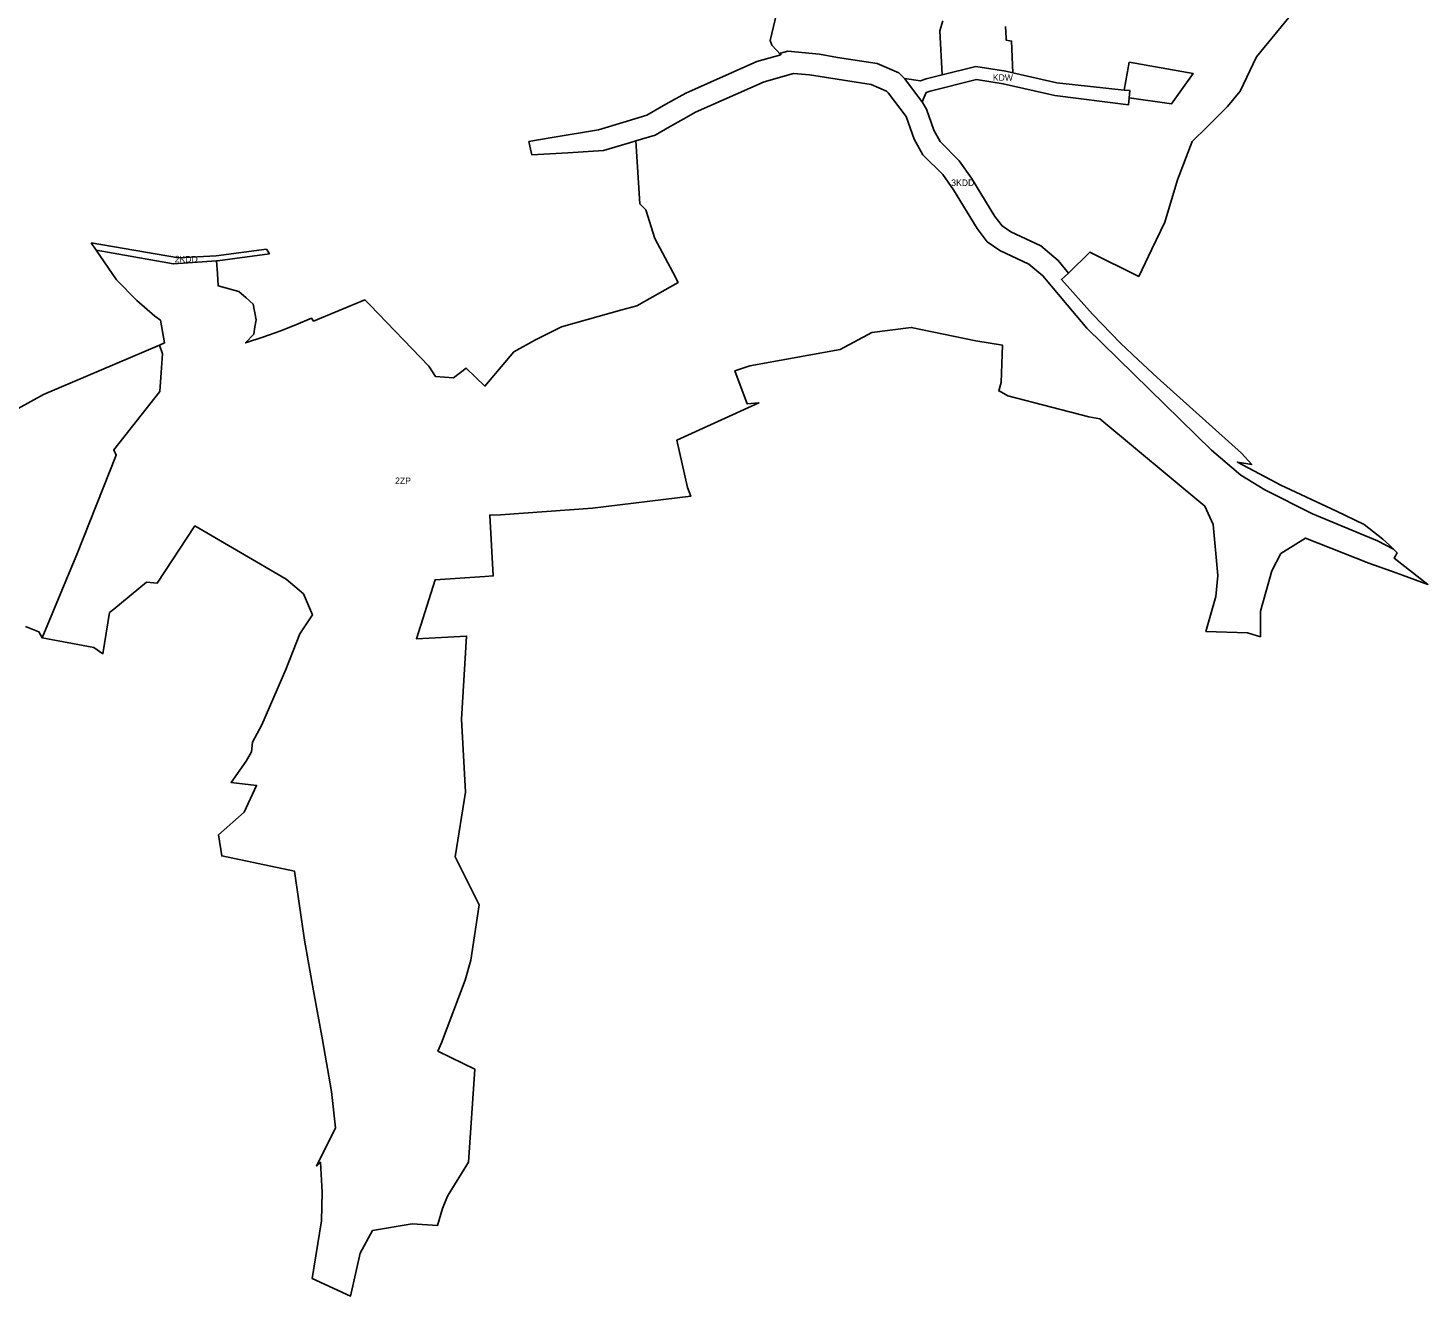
# Model space of a CAD drawing. Extents: x 7426456 to 7427896, y 5541728 to 5542811.
# Drawn here: x 7427071 to 7427722, y 5541728 to 5542318 of the extents above; entities that cross this region are included whole.
import ezdxf

# ---------------------------------------------------------------- set-up
doc = ezdxf.new("R2010")
doc.units = 0
doc.layers.add('ramka', color=7, linetype='Continuous')
doc.layers.add('sekcje2000', color=7, linetype='Continuous')

msp = doc.modelspace()

# ---------------------------------------------------------------- linework, layer by layer
at = {"layer": 'ramka'}
for points in [[(7427496.62, 5542321.43), (7427495.24, 5542316.82), (7427496.34, 5542296.34), (7427488.95, 5542294.5), (7427486.2, 5542293.52), (7427478.78, 5542294.55), (7427476.22, 5542297.19), (7427466.05, 5542301.59), (7427447.67, 5542304.4), (7427439.25, 5542305.92), (7427424.55, 5542307.28), (7427421.15, 5542306.43), (7427421.34, 5542305.69), (7427417.08, 5542310.1), (7427416.45, 5542312.28), (7427419.51, 5542325.3)], [(7427657.46, 5542322.96), (7427642.47, 5542304.62), (7427634.92, 5542288.78), (7427629.03, 5542281.65), (7427626.45, 5542279.09), (7427619.52, 5542272.18), (7427612.58, 5542265.27), (7427605.78, 5542247.45), (7427599.92, 5542227.83), (7427593.81, 5542215.19), (7427587.71, 5542202.55), (7427564.92, 5542213.86), (7427555.13, 5542204.17), (7427550.26, 5542209.98), (7427542.13, 5542216.77), (7427528.19, 5542223.34), (7427524.23, 5542226.08), (7427520.81, 5542230.48), (7427509.96, 5542248.34), (7427504.28, 5542256.36), (7427495.42, 5542265.27), (7427492.46, 5542270.54), (7427488.98, 5542280.32), (7427487.08, 5542283.7), (7427488.85, 5542288.09), (7427490.69, 5542288.75), (7427512.27, 5542294.13), (7427524.77, 5542292.17), (7427548.69, 5542286.73), (7427582.89, 5542282.31), (7427583.25, 5542285.64), (7427603, 5542282.87), (7427613.01, 5542296.9), (7427583.33, 5542302.2), (7427581, 5542289.26), (7427549.68, 5542292.66), (7427529.2, 5542297.32), (7427528.6, 5542311.99), (7427526.1, 5542312.44), (7427526.11, 5542313.47), (7427525.84, 5542318.74)], [(7427077.9, 5542034.45), (7427092.13, 5542068.44), (7427094.14, 5542073.22), (7427112.37, 5542119.39), (7427111.26, 5542121.9), (7427132.7, 5542149.07), (7427133.28, 5542157.84), (7427133.86, 5542166.61), (7427132.48, 5542170.67), (7427134.87, 5542171.69), (7427132.97, 5542182.19), (7427130.32, 5542184.07), (7427121.91, 5542191.44), (7427112.47, 5542200.95), (7427103.11, 5542214.83), (7427138.94, 5542208.4), (7427159, 5542209.8), (7427159.39, 5542203.97), (7427159.78, 5542198.14), (7427169.42, 5542195.64), (7427172.75, 5542192.62), (7427176.09, 5542189.61), (7427177.4, 5542182.35), (7427176.87, 5542179.07), (7427176.33, 5542175.79), (7427172.5, 5542171.66), (7427180.46, 5542174.36), (7427188.41, 5542177.06), (7427195.81, 5542180.08), (7427203.2, 5542183.1), (7427204.06, 5542181.79), (7427227.97, 5542191.72), (7427230.33, 5542189.4), (7427257.73, 5542160.87), (7427260.74, 5542156.06), (7427269.24, 5542155.41), (7427275.05, 5542159.95), (7427283.81, 5542151.56), (7427297.16, 5542167.51), (7427307.24, 5542173.02), (7427319.37, 5542179.14), (7427331.44, 5542182.53), (7427347.41, 5542187.03), (7427354.37, 5542188.93), (7427373.66, 5542199.76), (7427371.07, 5542204.61), (7427362.76, 5542220.14), (7427358.54, 5542233.49), (7427355.73, 5542236.3), (7427353.99, 5542265.61), (7427362.98, 5542268.32), (7427369.64, 5542272.11), (7427376.3, 5542275.89), (7427381.65, 5542278.91), (7427413.57, 5542293.07), (7427427.28, 5542296.99), (7427434.71, 5542296.3), (7427434.7, 5542296.27), (7427463.26, 5542291.9), (7427470.43, 5542288.8), (7427471.21, 5542288), (7427479.56, 5542276.96), (7427483.33, 5542266.38), (7427487.38, 5542259.19), (7427496.6, 5542249.9), (7427501.6, 5542242.85), (7427512.57, 5542224.79), (7427517.28, 5542218.74), (7427523.18, 5542214.65), (7427536.7, 5542208.27), (7427543.17, 5542202.88), (7427554.43, 5542189.41), (7427563.54, 5542178.56), (7427621.54, 5542121.81), (7427635.23, 5542110.1), (7427646.32, 5542103.34), (7427668.48, 5542092.2), (7427698.75, 5542079.63), (7427706.17, 5542075.74), (7427707.83, 5542074.04), (7427706.52, 5542071.51), (7427722.19, 5542059.39), (7427707.34, 5542064.8), (7427694.72, 5542069.26), (7427665.28, 5542080.91), (7427653.79, 5542073.66), (7427649.62, 5542065.74), (7427644.37, 5542046.92), (7427644.26, 5542035.03), (7427638.22, 5542036.86), (7427618.93, 5542037.47), (7427623.56, 5542053.8), (7427624.55, 5542063.47), (7427622.34, 5542087.19), (7427618.51, 5542095.75), (7427569.69, 5542136.33), (7427564.56, 5542137.21), (7427547.22, 5542141.71), (7427526.89, 5542146.99), (7427522.87, 5542149.31)], [(7427522.87, 5542149.31), (7427522.64, 5542149.35), (7427523.75, 5542153.22), (7427524.44, 5542170.54), (7427512.06, 5542172.69), (7427481.97, 5542178.83), (7427463.6, 5542176.47), (7427448.85, 5542168.64), (7427406.98, 5542161.01), (7427400.03, 5542158.74), (7427405.7, 5542143.31), (7427411.19, 5542143.75), (7427372.95, 5542126.39), (7427377.88, 5542104.45), (7427379.55, 5542100.44), (7427333.84, 5542094.75), (7427291.09, 5542091.66), (7427286.03, 5542091.6), (7427287.67, 5542063.32), (7427283.68, 5542063.1), (7427260.63, 5542061.54), (7427251.9, 5542034.07), (7427275.29, 5542035.31), (7427272.9, 5541996.7), (7427274.68, 5541962.76), (7427269.98, 5541932.67), (7427281.12, 5541910.36), (7427277.24, 5541884.7), (7427274.54, 5541875.37), (7427263.58, 5541846.14), (7427261.96, 5541842.37), (7427279.11, 5541833.87), (7427276.07, 5541790.66), (7427266.42, 5541774.91), (7427264.05, 5541769.12), (7427261.74, 5541761.3), (7427249.89, 5541762.01), (7427231.58, 5541758.87), (7427225.77, 5541748.32), (7427221.33, 5541728.45), (7427203.44, 5541736.61), (7427207.76, 5541763.36), (7427208.1, 5541776.78), (7427207.37, 5541790.65), (7427205.56, 5541788.84), (7427214.31, 5541806.68), (7427212.49, 5541823.6), (7427208.2, 5541847.61), (7427204.14, 5541870.31), (7427199.92, 5541893.94), (7427197.24, 5541912.13), (7427195.33, 5541926.01), (7427161.43, 5541933.11), (7427159.93, 5541942.91), (7427171.89, 5541953.37), (7427177.64, 5541965.86), (7427165.75, 5541967.31), (7427172.73, 5541977.13), (7427175.26, 5541981.48), (7427175.75, 5541985.99), (7427180.07, 5541994.1), (7427185.62, 5542006.94), (7427191.17, 5542019.78), (7427197.79, 5542036.36), (7427203.6, 5542045.19), (7427199.44, 5542054.95), (7427191.39, 5542061.83), (7427148.94, 5542086.56), (7427131.44, 5542059.97), (7427126.41, 5542060.46), (7427111.28, 5542047.84), (7427109.33, 5542046.22), (7427106.18, 5542027.1), (7427101.97, 5542029.99), (7427077.9, 5542034.45)], [(7427066.85, 5542141.19), (7427078.62, 5542147.67), (7427132.48, 5542170.67), (7427133.86, 5542166.61), (7427133.28, 5542157.84), (7427132.7, 5542149.07), (7427111.26, 5542121.9), (7427112.37, 5542119.39), (7427094.14, 5542073.22), (7427092.13, 5542068.44), (7427077.9, 5542034.45), (7427076.46, 5542037.26), (7427070.23, 5542039.71)]]:
    msp.add_lwpolyline(points, dxfattribs=at)
for points in [[(7427304.17, 5542265.38), (7427314.04, 5542267.08), (7427336.62, 5542270.82), (7427347.82, 5542274.19), (7427359.02, 5542277.57), (7427367.87, 5542282.62), (7427377.16, 5542287.85), (7427410.15, 5542302.49), (7427421.34, 5542305.69), (7427421.15, 5542306.43), (7427424.55, 5542307.28), (7427439.25, 5542305.92), (7427447.67, 5542304.4), (7427466.05, 5542301.59), (7427476.22, 5542297.19), (7427478.78, 5542294.55), (7427486.95, 5542283.93), (7427487.08, 5542283.7), (7427488.98, 5542280.32), (7427492.46, 5542270.54), (7427495.42, 5542265.27), (7427504.28, 5542256.36), (7427509.96, 5542248.34), (7427520.81, 5542230.48), (7427524.23, 5542226.08), (7427528.19, 5542223.34), (7427542.13, 5542216.77), (7427550.26, 5542209.98), (7427555.13, 5542204.17), (7427551.79, 5542201.2), (7427566.23, 5542185.02), (7427579.2, 5542171.61), (7427587.5, 5542163.8), (7427596.32, 5542155.51), (7427635.47, 5542120.46), (7427640.22, 5542115.06), (7427633.63, 5542116.27), (7427653.78, 5542105.46), (7427679.59, 5542093.49), (7427692.46, 5542087.22), (7427701.17, 5542080.38), (7427704.33, 5542077.61), (7427706.17, 5542075.74), (7427698.75, 5542079.63), (7427668.48, 5542092.2), (7427646.32, 5542103.34), (7427635.23, 5542110.1), (7427621.54, 5542121.81), (7427563.54, 5542178.56), (7427554.43, 5542189.41), (7427543.17, 5542202.88), (7427536.7, 5542208.27), (7427523.18, 5542214.65), (7427517.28, 5542218.74), (7427512.57, 5542224.79), (7427501.6, 5542242.85), (7427496.6, 5542249.9), (7427487.38, 5542259.19), (7427483.33, 5542266.38), (7427479.56, 5542276.96), (7427471.21, 5542288), (7427470.43, 5542288.8), (7427463.26, 5542291.9), (7427434.7, 5542296.27), (7427434.71, 5542296.3), (7427427.28, 5542296.99), (7427413.57, 5542293.07), (7427381.65, 5542278.91), (7427376.3, 5542275.89), (7427369.64, 5542272.11), (7427362.98, 5542268.32), (7427353.99, 5542265.61), (7427350.94, 5542264.69), (7427338.89, 5542261.06), (7427322.25, 5542260.06), (7427305.6, 5542259.05), (7427304.99, 5542261.72)], [(7427478.78, 5542294.55), (7427486.2, 5542293.52), (7427488.95, 5542294.5), (7427496.34, 5542296.34), (7427512, 5542300.25), (7427525.9, 5542298.07), (7427529.2, 5542297.32), (7427549.68, 5542292.66), (7427581, 5542289.26), (7427583.61, 5542288.98), (7427583.25, 5542285.64), (7427582.89, 5542282.31), (7427548.69, 5542286.73), (7427524.77, 5542292.17), (7427512.27, 5542294.13), (7427490.69, 5542288.75), (7427488.85, 5542288.09), (7427487.08, 5542283.7), (7427486.95, 5542283.93)], [(7427100.81, 5542218.24), (7427141.32, 5542211.24), (7427158.85, 5542212.21), (7427182.17, 5542215.32), (7427183.58, 5542213.16), (7427159.43, 5542209.83), (7427159, 5542209.8), (7427138.94, 5542208.4), (7427103.11, 5542214.83), (7427103.11, 5542214.83)]]:
    msp.add_lwpolyline(points, close=True, dxfattribs=at)

# ---------------------------------------------------------------- texts
at = {"layer": 'sekcje2000'}
for s, p in [('KDW', (7427519.88, 5542293.56)), ('3KDD', (7427500.56, 5542244.66)), ('2KDD', (7427139.58, 5542209.14)), ('2ZP', (7427242.03, 5542106.06))]:
    msp.add_text(s, height=3, dxfattribs=at).set_placement(p)

doc.saveas('drawing.dxf')
